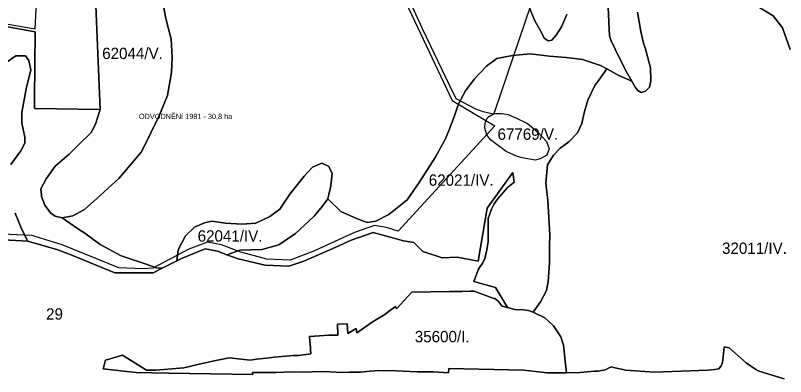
# Model space of a CAD drawing. Extents: x -521621 to -516761, y -1190184 to -1184927.
# Drawn here: x -519686 to -518666, y -1187173 to -1186696 of the extents above; entities that cross this region are included whole.
import ezdxf

# ---------------------------------------------------------------- set-up
doc = ezdxf.new("R2010")
doc.units = 0
doc.layers.add('BPEJ_s', color=7, linetype='Continuous')
doc.layers.add('odvodneni_s', color=7, linetype='Continuous')

msp = doc.modelspace()

# ---------------------------------------------------------------- linework, layer by layer
at = {"layer": 'BPEJ_s'}
for p, q in [((-519061.2, -1186950.7), (-519027.5, -1186903.5)), ((-519027.5, -1186903.5), (-519025.7, -1186916.1)), ((-519025.7, -1186916.1), (-519034.2, -1186923.4)), ((-519034.2, -1186923.4), (-519047.7, -1186938.8)), ((-519052.2, -1186945), (-519055.4, -1186952)), ((-519047.7, -1186938.8), (-519052.2, -1186945)), ((-519073.3, -1187020.7), (-519061.2, -1186950.7)), ((-519055.4, -1186952), (-519060.1, -1186964.4)), ((-519060.1, -1186964.4), (-519060.1, -1186994.7)), ((-519241.2, -1186992.8), (-519212, -1186982.9)), ((-519212, -1186982.9), (-519172, -1186993.8)), ((-519717.5, -1186991.5), (-519669.4, -1186994.1)), ((-519669.4, -1186994.1), (-519629.4, -1187005.5)), ((-519262.3, -1187002.7), (-519241.2, -1186992.8)), ((-519172, -1186993.8), (-519158.4, -1186996.1)), ((-519158.4, -1186996.1), (-519146.6, -1187007.9)), ((-519060.1, -1186994.7), (-519061.7, -1187005.5)), ((-519629.4, -1187005.5), (-519613.1, -1187012)), ((-519465.9, -1187017.1), (-519434.5, -1187004.2)), ((-519434.5, -1187004.2), (-519418.3, -1187007.6)), ((-519418.3, -1187007.6), (-519405.7, -1187012.2)), ((-519303.9, -1187020.8), (-519262.3, -1187002.7)), ((-519146.6, -1187007.9), (-519120.8, -1187016.4)), ((-519061.7, -1187005.5), (-519064.2, -1187017.2)), ((-519613.1, -1187012), (-519553.9, -1187036.2)), ((-519472, -1187020.2), (-519465.9, -1187017.1)), ((-519405.7, -1187012.2), (-519390.7, -1187017.7)), ((-519390.7, -1187017.7), (-519355.3, -1187026)), ((-519120.8, -1187016.4), (-519100.9, -1187015.3)), ((-519100.9, -1187015.3), (-519073.3, -1187020.7)), ((-519064.2, -1187017.2), (-519067.6, -1187023.9)), ((-519503.2, -1187036.2), (-519491.3, -1187030.1)), ((-519491.3, -1187030.1), (-519472, -1187020.2)), ((-519355.3, -1187026), (-519323.8, -1187027.2)), ((-519323.8, -1187027.2), (-519303.9, -1187020.8)), ((-519070.4, -1187027.8), (-519073.4, -1187031.9)), ((-519067.6, -1187023.9), (-519070.4, -1187027.8)), ((-519553.9, -1187036.2), (-519503.2, -1187036.2)), ((-519073.4, -1187031.9), (-519078.8, -1187047.4)), ((-519078.8, -1187047.4), (-519050.4, -1187055.5)), ((-519110.8, -1187060.8), (-519160.9, -1187061.6)), ((-519094.7, -1187060.6), (-519110.8, -1187060.8)), ((-519083.9, -1187060.1), (-519094.7, -1187060.6)), ((-519078.6, -1187060.1), (-519083.9, -1187060.1)), ((-519052.5, -1187069.8), (-519078.6, -1187060.1)), ((-519050.4, -1187055.5), (-519034.3, -1187082.1)), ((-519160.9, -1187061.6), (-519181.5, -1187083.7)), ((-519051.2, -1187070), (-519052.5, -1187069.8)), ((-519046.6, -1187073.7), (-519051.2, -1187070)), ((-519182.6, -1187080.6), (-519190.4, -1187086.5)), ((-519181.5, -1187083.7), (-519182.6, -1187080.6)), ((-519041.4, -1187080.2), (-519046.6, -1187073.7)), ((-519034.3, -1187082.1), (-519041.4, -1187080.2)), ((-519196.7, -1187091.3), (-519212, -1187100.5)), ((-519190.4, -1187086.5), (-519196.7, -1187091.3)), ((-519212, -1187100.5), (-519233.7, -1187115.4)), ((-519246.5, -1187103.5), (-519259.6, -1187104)), ((-519259.6, -1187104), (-519258.9, -1187118.4)), ((-519245.5, -1187116.5), (-519246.5, -1187103.5)), ((-519234.5, -1187109.6), (-519245.5, -1187116.5)), ((-519233.7, -1187115.4), (-519234.5, -1187109.6)), ((-519283.3, -1187119.5), (-519296.6, -1187120.3)), ((-519296.6, -1187120.3), (-519296.1, -1187126.4)), ((-519270.7, -1187118.4), (-519283.3, -1187119.5)), ((-519258.9, -1187118.4), (-519270.7, -1187118.4)), ((-519296.1, -1187126.4), (-519295.3, -1187134.7)), ((-519295.3, -1187134.7), (-519295.1, -1187137.5)), ((-519295.1, -1187137.5), (-519294.6, -1187143.4)), ((-518749.4, -1187151.7), (-518747.8, -1187133.9)), ((-518747.8, -1187133.9), (-518741, -1187135.4)), ((-518741, -1187135.4), (-518718.6, -1187155)), ((-519566.6, -1187151.5), (-519569.4, -1187162.9)), ((-519543.8, -1187144.9), (-519566.6, -1187151.5)), ((-519512.1, -1187164.9), (-519543.8, -1187144.9)), ((-519420.3, -1187151.8), (-519442.3, -1187156.7)), ((-519402.6, -1187148.6), (-519420.3, -1187151.8)), ((-519375, -1187151.4), (-519402.6, -1187148.6)), ((-519366.6, -1187150.2), (-519375, -1187151.4)), ((-519353.4, -1187149), (-519366.6, -1187150.2)), ((-519343.4, -1187147.8), (-519353.4, -1187149)), ((-519332.9, -1187146.6), (-519343.4, -1187147.8)), ((-519318, -1187145.5), (-519332.9, -1187146.6)), ((-519310.7, -1187145.4), (-519318, -1187145.5)), ((-519294.6, -1187143.4), (-519310.7, -1187145.4)), ((-518750.3, -1187156.3), (-518749.4, -1187151.7)), ((-519462.7, -1187161.5), (-519499.6, -1187164.9)), ((-519442.3, -1187156.7), (-519462.7, -1187161.5)), ((-519112.7, -1187168.2), (-519112.1, -1187162.7)), ((-519112.1, -1187162.7), (-519012.8, -1187164.8)), ((-518905.2, -1187164.5), (-518897.3, -1187160.6)), ((-518897.3, -1187160.6), (-518894, -1187161.4)), ((-518894, -1187161.4), (-518877.6, -1187164.9)), ((-518754.9, -1187162.9), (-518751.8, -1187159)), ((-518751.8, -1187159), (-518750.3, -1187156.3)), ((-518718.6, -1187155), (-518705.9, -1187164)), ((-519569.4, -1187162.9), (-519526.2, -1187167.7)), ((-519526.2, -1187167.7), (-519482.7, -1187168.7)), ((-519499.6, -1187164.9), (-519512.1, -1187164.9)), ((-519482.7, -1187168.7), (-519371.4, -1187170.7)), ((-519371.4, -1187170.7), (-519371.8, -1187168.1)), ((-519371.8, -1187168.1), (-519361.1, -1187168.1)), ((-519361.1, -1187168.1), (-519349.9, -1187167.9)), ((-519349.9, -1187167.9), (-519340.9, -1187167.8)), ((-519340.9, -1187167.8), (-519330.4, -1187167.5)), ((-519330.4, -1187167.5), (-519317.6, -1187167.2)), ((-519317.6, -1187167.2), (-519304.5, -1187167.6)), ((-519304.5, -1187167.6), (-519292.7, -1187167)), ((-519292.7, -1187167), (-519282.1, -1187166.5)), ((-519282.1, -1187166.5), (-519269, -1187166.9)), ((-519269, -1187166.9), (-519253.7, -1187167.9)), ((-519253.7, -1187167.9), (-519243.6, -1187167.4)), ((-519243.6, -1187167.4), (-519229, -1187167.4)), ((-519229, -1187167.4), (-519216, -1187166.1)), ((-519216, -1187166.1), (-519204.7, -1187165.1)), ((-519204.7, -1187165.1), (-519197.9, -1187165.6)), ((-519197.9, -1187165.6), (-519191.8, -1187165.2)), ((-519191.8, -1187165.2), (-519153.7, -1187166.8)), ((-519153.7, -1187166.8), (-519132.6, -1187166.8)), ((-519132.6, -1187166.8), (-519112.7, -1187168.2)), ((-519012.8, -1187164.8), (-518989.2, -1187167.6)), ((-518989.2, -1187167.6), (-518982, -1187168.3)), ((-518982, -1187168.3), (-518956.3, -1187168.5)), ((-518956.3, -1187168.5), (-518938.3, -1187168.1)), ((-518938.3, -1187168.1), (-518919.4, -1187166.2)), ((-518919.4, -1187166.2), (-518914.3, -1187166)), ((-518914.3, -1187166), (-518905.2, -1187164.5)), ((-518877.6, -1187164.9), (-518839.9, -1187167.3)), ((-518839.9, -1187167.3), (-518792.7, -1187165.9)), ((-518792.7, -1187165.9), (-518769.1, -1187164.9)), ((-518769.1, -1187164.9), (-518760.6, -1187164)), ((-518760.6, -1187164), (-518754.9, -1187162.9)), ((-518705.9, -1187164), (-518702.8, -1187165.7)), ((-518702.8, -1187165.7), (-518688.4, -1187170)), ((-518688.4, -1187170), (-518668.2, -1187176.1))]:
    msp.add_line(p, q, dxfattribs=at)
for points in [[(-519579.6, -1186671.4), (-519573.7, -1186819.9), (-519660.4, -1186818.6), (-519660.2, -1186805.4), (-519659.7, -1186717.4), (-519752.1, -1186700.7)], [(-519489.7, -1186683.4), (-519486.6, -1186699.5), (-519479.5, -1186727), (-519478.3, -1186750.9), (-519478.9, -1186771.3), (-519484.5, -1186801.4), (-519495.9, -1186829.2), (-519506.3, -1186850.9), (-519518.7, -1186876.2), (-519548.7, -1186911.4), (-519577.7, -1186937.6), (-519594.4, -1186952.4), (-519609.6, -1186960.5), (-519623.9, -1186963.3), (-519632.9, -1186961), (-519639.1, -1186956.7), (-519646.8, -1186946.7), (-519651.1, -1186934.9), (-519651.1, -1186932.7), (-519652, -1186924.8), (-519644.8, -1186911.9), (-519632.9, -1186895.2), (-519614.4, -1186879), (-519603.2, -1186867.6), (-519585.4, -1186850.6), (-519579.6, -1186839.5), (-519573.7, -1186819.9), (-519579.6, -1186671.4)], [(-518901.2, -1186685.2), (-518899.4, -1186722.4), (-518897, -1186729.3), (-518886.5, -1186751.3), (-518876.8, -1186770.2), (-518870, -1186782.6), (-518887, -1186775.1), (-518902.9, -1186766.4), (-518911.3, -1186762), (-518920.6, -1186758.6), (-518935.1, -1186753.9), (-518956.8, -1186751.4), (-518978.8, -1186749.3), (-519004.5, -1186746.5), (-519028, -1186748.4), (-519048.4, -1186752.7), (-519062, -1186762.7), (-519078.1, -1186779.4), (-519090.2, -1186795.2), (-519099.2, -1186812.5), (-519104.7, -1186828.6), (-519111.8, -1186846.9), (-519117.1, -1186859.9), (-519120.8, -1186866.6), (-519130, -1186883.3), (-519151.4, -1186916.7), (-519167.3, -1186939.7), (-519191.5, -1186958.8), (-519208.6, -1186967.9), (-519220.1, -1186969.5), (-519234.4, -1186964.3), (-519255, -1186954.8), (-519272.1, -1186938.1), (-519268.1, -1186921), (-519266.5, -1186904.7), (-519270.9, -1186895.6), (-519280, -1186891.2), (-519292.3, -1186896.4), (-519303.4, -1186908.3), (-519322.5, -1186931.8), (-519335.6, -1186952), (-519349.1, -1186961.5), (-519367.4, -1186970.3), (-519386, -1186971.9), (-519407.8, -1186970.3), (-519425.7, -1186967.9), (-519435.6, -1186969.9), (-519448.7, -1186975.8), (-519460.6, -1186987), (-519470.2, -1187005.6), (-519472, -1187020.2), (-519491.3, -1187030.1), (-519499, -1187029.5), (-519513.9, -1187024.1), (-519545.5, -1187013.4), (-519573.3, -1186998.5), (-519593.9, -1186983.8), (-519603.4, -1186977.6), (-519623.9, -1186963.3), (-519609.6, -1186960.5), (-519594.4, -1186952.4), (-519577.7, -1186937.6), (-519548.7, -1186911.4), (-519518.7, -1186876.2), (-519506.3, -1186850.9), (-519495.9, -1186829.2), (-519484.5, -1186801.4), (-519478.9, -1186771.3), (-519478.3, -1186750.9), (-519479.5, -1186727), (-519486.6, -1186699.5), (-519489.7, -1186683.4)], [(-518955.8, -1186694.2), (-518963.1, -1186710.9), (-518970.1, -1186721.8), (-518975.7, -1186728.5), (-518980.7, -1186729.1), (-518985.7, -1186725.8), (-518988.7, -1186719.8), (-518998.6, -1186701.9), (-519006.3, -1186683.5)], [(-519006.3, -1186683.5), (-518998.6, -1186701.9), (-518988.7, -1186719.8), (-518985.7, -1186725.8), (-518980.7, -1186729.1), (-518975.7, -1186728.5), (-518970.1, -1186721.8), (-518963.1, -1186710.9), (-518955.8, -1186694.2)], [(-518668.2, -1187176.1), (-518688.4, -1187170), (-518702.8, -1187165.7), (-518705.9, -1187164), (-518718.6, -1187155), (-518741, -1187135.4), (-518747.8, -1187133.9), (-518749.4, -1187151.7), (-518750.3, -1187156.3), (-518751.8, -1187159), (-518754.9, -1187162.9), (-518760.6, -1187164), (-518769.1, -1187164.9), (-518792.7, -1187165.9), (-518839.9, -1187167.3), (-518877.6, -1187164.9), (-518894, -1187161.4), (-518897.3, -1187160.6), (-518905.2, -1187164.5), (-518914.3, -1187166), (-518919.4, -1187166.2), (-518938.3, -1187168.1), (-518956.3, -1187168.5), (-518958.2, -1187153), (-518960.5, -1187131.7), (-518963.8, -1187120.9), (-518973.7, -1187106), (-518985.1, -1187095.8), (-519000.4, -1187088.2), (-518990.8, -1187074.3), (-518982.6, -1187059.6), (-518980.8, -1187047.5), (-518978.9, -1187023.1), (-518978.6, -1187000.9), (-518978.5, -1186986), (-518980.9, -1186940.5), (-518983.6, -1186917.6), (-518981.4, -1186893.1), (-518973.5, -1186880.3), (-518964.5, -1186871.3), (-518953.2, -1186862.6), (-518941.6, -1186851.1), (-518936.2, -1186838.6), (-518932.8, -1186824.5), (-518928, -1186807.8), (-518918.9, -1186788.1), (-518913.6, -1186781.3), (-518902.9, -1186766.4), (-518887, -1186775.1), (-518870, -1186782.6), (-518865.5, -1186790.3), (-518861.8, -1186794.8), (-518857.4, -1186797.7), (-518851.6, -1186795.7), (-518846.6, -1186790.4), (-518844.9, -1186781.9), (-518845.1, -1186764.9), (-518852.2, -1186738.4), (-518854.4, -1186732.1), (-518857.9, -1186716.8), (-518862.2, -1186691.2)], [(-518862.2, -1186691.2), (-518857.9, -1186716.8), (-518854.4, -1186732.1), (-518852.2, -1186738.4), (-518845.1, -1186764.9), (-518844.9, -1186781.9), (-518846.6, -1186790.4), (-518851.6, -1186795.7), (-518857.4, -1186797.7), (-518861.8, -1186794.8), (-518865.5, -1186790.3), (-518870, -1186782.6), (-518876.8, -1186770.2), (-518886.5, -1186751.3), (-518897, -1186729.3), (-518899.4, -1186722.4), (-518901.2, -1186685.2)], [(-518660.4, -1186740.5), (-518670.3, -1186712), (-518683, -1186696.2), (-518703, -1186683.7)], [(-518703, -1186683.7), (-518683, -1186696.2), (-518670.3, -1186712), (-518660.4, -1186740.5)], [(-519752.1, -1186700.7), (-519659.7, -1186717.4), (-519660.2, -1186805.4), (-519660.4, -1186818.6), (-519573.7, -1186819.9), (-519579.6, -1186839.5), (-519585.4, -1186850.6), (-519603.2, -1186867.6), (-519614.4, -1186879), (-519632.9, -1186895.2), (-519644.8, -1186911.9), (-519652, -1186924.8), (-519651.1, -1186932.7), (-519651.1, -1186934.9), (-519646.8, -1186946.7), (-519639.1, -1186956.7), (-519632.9, -1186961), (-519623.9, -1186963.3), (-519603.4, -1186977.6), (-519593.9, -1186983.8), (-519573.3, -1186998.5), (-519545.5, -1187013.4), (-519513.9, -1187024.1), (-519499, -1187029.5), (-519491.3, -1187030.1), (-519503.2, -1187036.2), (-519553.9, -1187036.2), (-519613.1, -1187012), (-519629.4, -1187005.5), (-519669.4, -1186994.1), (-519677.2, -1186978.6), (-519685.8, -1186957.2)], [(-519697.7, -1186758), (-519685.3, -1186749), (-519672.5, -1186749), (-519667.7, -1186755.2), (-519665.3, -1186767.6), (-519671.5, -1186792.8), (-519677.2, -1186823.8), (-519677.2, -1186838.1), (-519673.4, -1186856.6), (-519673.4, -1186864.7), (-519678.7, -1186874.7), (-519691.5, -1186892.8)], [(-519691.5, -1186892.8), (-519678.7, -1186874.7), (-519673.4, -1186864.7), (-519673.4, -1186856.6), (-519677.2, -1186838.1), (-519677.2, -1186823.8), (-519671.5, -1186792.8), (-519665.3, -1186767.6), (-519667.7, -1186755.2), (-519672.5, -1186749), (-519685.3, -1186749), (-519697.7, -1186758)], [(-519685.8, -1186957.2), (-519677.2, -1186978.6), (-519669.4, -1186994.1), (-519717.5, -1186991.5)]]:
    msp.add_lwpolyline(points, dxfattribs=at)
for points in [[(-519405.7, -1187012.2), (-519388.8, -1187006), (-519359.4, -1187005.2), (-519337.2, -1186998.9), (-519315, -1186984.2), (-519290.3, -1186961.1), (-519279.6, -1186948.4), (-519272.1, -1186938.1), (-519255, -1186954.8), (-519234.4, -1186964.3), (-519220.1, -1186969.5), (-519208.6, -1186967.9), (-519191.5, -1186958.8), (-519167.3, -1186939.7), (-519151.4, -1186916.7), (-519130, -1186883.3), (-519120.8, -1186866.6), (-519117.1, -1186859.9), (-519111.8, -1186846.9), (-519104.7, -1186828.6), (-519099.2, -1186812.5), (-519090.2, -1186795.2), (-519078.1, -1186779.4), (-519062, -1186762.7), (-519048.4, -1186752.7), (-519028, -1186748.4), (-519004.5, -1186746.5), (-518978.8, -1186749.3), (-518956.8, -1186751.4), (-518935.1, -1186753.9), (-518920.6, -1186758.6), (-518911.3, -1186762), (-518902.9, -1186766.4), (-518913.6, -1186781.3), (-518918.9, -1186788.1), (-518928, -1186807.8), (-518932.8, -1186824.5), (-518936.2, -1186838.6), (-518941.6, -1186851.1), (-518953.2, -1186862.6), (-518964.5, -1186871.3), (-518973.5, -1186880.3), (-518981.4, -1186893.1), (-518983.6, -1186917.6), (-518980.9, -1186940.5), (-518978.5, -1186986), (-518978.6, -1187000.9), (-518978.9, -1187023.1), (-518980.8, -1187047.5), (-518982.6, -1187059.6), (-518990.8, -1187074.3), (-519000.4, -1187088.2), (-519006.5, -1187085.9), (-519013.1, -1187084.8), (-519024.5, -1187084.6), (-519034.3, -1187082.1), (-519050.4, -1187055.5), (-519078.8, -1187047.4), (-519073.4, -1187031.9), (-519070.4, -1187027.8), (-519067.6, -1187023.9), (-519064.2, -1187017.2), (-519061.7, -1187005.5), (-519060.1, -1186994.7), (-519060.1, -1186964.4), (-519055.4, -1186952), (-519052.2, -1186945), (-519047.7, -1186938.8), (-519034.2, -1186923.4), (-519025.7, -1186916.1), (-519027.5, -1186903.5), (-519061.2, -1186950.7), (-519073.3, -1187020.7), (-519100.9, -1187015.3), (-519120.8, -1187016.4), (-519146.6, -1187007.9), (-519158.4, -1186996.1), (-519172, -1186993.8), (-519212, -1186982.9), (-519241.2, -1186992.8), (-519262.3, -1187002.7), (-519303.9, -1187020.8), (-519323.8, -1187027.2), (-519355.3, -1187026), (-519390.7, -1187017.7)], [(-519052, -1186825.3), (-519042.4, -1186825.3), (-519033.4, -1186826.8), (-519022.6, -1186831.6), (-519008, -1186838.6), (-518994.2, -1186849.8), (-518982.6, -1186862.4), (-518979.4, -1186872), (-518982.2, -1186880.3), (-518991.1, -1186885.5), (-518997.7, -1186887.1), (-519014.8, -1186884), (-519022.4, -1186881.6), (-519036.3, -1186875.5), (-519053.2, -1186862.6), (-519057.1, -1186860.1), (-519061.7, -1186853.5), (-519064.5, -1186844.5), (-519064, -1186837.1), (-519060.6, -1186830.2)], [(-519052, -1186825.3), (-519042.4, -1186825.3), (-519033.4, -1186826.8), (-519022.6, -1186831.6), (-519008, -1186838.6), (-518994.2, -1186849.8), (-518982.6, -1186862.4), (-518979.4, -1186872), (-518982.2, -1186880.3), (-518991.1, -1186885.5), (-518997.7, -1186887.1), (-519014.8, -1186884), (-519022.4, -1186881.6), (-519036.3, -1186875.5), (-519053.2, -1186862.6), (-519057.1, -1186860.1), (-519061.7, -1186853.5), (-519064.5, -1186844.5), (-519064, -1186837.1), (-519060.6, -1186830.2)], [(-519472, -1187020.2), (-519470.2, -1187005.6), (-519460.6, -1186987), (-519448.7, -1186975.8), (-519435.6, -1186969.9), (-519425.7, -1186967.9), (-519407.8, -1186970.3), (-519386, -1186971.9), (-519367.4, -1186970.3), (-519349.1, -1186961.5), (-519335.6, -1186952), (-519322.5, -1186931.8), (-519303.4, -1186908.3), (-519292.3, -1186896.4), (-519280, -1186891.2), (-519270.9, -1186895.6), (-519266.5, -1186904.7), (-519268.1, -1186921), (-519272.1, -1186938.1), (-519279.6, -1186948.4), (-519290.3, -1186961.1), (-519315, -1186984.2), (-519337.2, -1186998.9), (-519359.4, -1187005.2), (-519388.8, -1187006), (-519405.7, -1187012.2), (-519418.3, -1187007.6), (-519434.5, -1187004.2), (-519465.9, -1187017.1)], [(-519034.3, -1187082.1), (-519024.5, -1187084.6), (-519013.1, -1187084.8), (-519006.5, -1187085.9), (-519000.4, -1187088.2), (-518985.1, -1187095.8), (-518973.7, -1187106), (-518963.8, -1187120.9), (-518960.5, -1187131.7), (-518958.2, -1187153), (-518956.3, -1187168.5), (-518982, -1187168.3), (-518989.2, -1187167.6), (-519012.8, -1187164.8), (-519112.1, -1187162.7), (-519112.7, -1187168.2), (-519132.6, -1187166.8), (-519153.7, -1187166.8), (-519191.8, -1187165.2), (-519197.9, -1187165.6), (-519204.7, -1187165.1), (-519216, -1187166.1), (-519229, -1187167.4), (-519243.6, -1187167.4), (-519253.7, -1187167.9), (-519269, -1187166.9), (-519282.1, -1187166.5), (-519292.7, -1187167), (-519304.5, -1187167.6), (-519317.6, -1187167.2), (-519330.4, -1187167.5), (-519340.9, -1187167.8), (-519349.9, -1187167.9), (-519361.1, -1187168.1), (-519371.8, -1187168.1), (-519371.4, -1187170.7), (-519482.7, -1187168.7), (-519526.2, -1187167.7), (-519569.4, -1187162.9), (-519566.6, -1187151.5), (-519543.8, -1187144.9), (-519512.1, -1187164.9), (-519499.6, -1187164.9), (-519462.7, -1187161.5), (-519442.3, -1187156.7), (-519420.3, -1187151.8), (-519402.6, -1187148.6), (-519375, -1187151.4), (-519366.6, -1187150.2), (-519353.4, -1187149), (-519343.4, -1187147.8), (-519332.9, -1187146.6), (-519318, -1187145.5), (-519310.7, -1187145.4), (-519294.6, -1187143.4), (-519295.1, -1187137.5), (-519295.3, -1187134.7), (-519296.1, -1187126.4), (-519296.6, -1187120.3), (-519283.3, -1187119.5), (-519270.7, -1187118.4), (-519258.9, -1187118.4), (-519259.6, -1187104), (-519246.5, -1187103.5), (-519245.5, -1187116.5), (-519234.5, -1187109.6), (-519233.7, -1187115.4), (-519212, -1187100.5), (-519196.7, -1187091.3), (-519190.4, -1187086.5), (-519182.6, -1187080.6), (-519181.5, -1187083.7), (-519160.9, -1187061.6), (-519110.8, -1187060.8), (-519094.7, -1187060.6), (-519083.9, -1187060.1), (-519078.6, -1187060.1), (-519052.5, -1187069.8), (-519051.2, -1187070), (-519046.6, -1187073.7), (-519041.4, -1187080.2)]]:
    msp.add_lwpolyline(points, close=True, dxfattribs=at)
at = {"layer": 'odvodneni_s'}
for points in [[(-519752.3, -1186697.3), (-519659.4, -1186713.5), (-519656.7, -1186661.9)], [(-519180.3, -1186654), (-519107.8, -1186808), (-519051.1, -1186841.6), (-519178.9, -1186981), (-519194.7, -1186976.3), (-519210.4, -1186973.4), (-519237, -1186982.9), (-519290, -1187006.8), (-519321.9, -1187019.1), (-519352.7, -1187018), (-519387.2, -1187008.8), (-519413.1, -1186998.9), (-519431.5, -1186995.3), (-519456.3, -1187004.9), (-519503.7, -1187029.7), (-519516.8, -1187030.9), (-519548.9, -1187029.5), (-519623.6, -1186999.2), (-519652.5, -1186990.2), (-519663.4, -1186986.8), (-519714.2, -1186984.7)], [(-519003.5, -1186681.4), (-519051.3, -1186821.6), (-519053.1, -1186826.2), (-519066.5, -1186823.3), (-519076.5, -1186819.5), (-519102.5, -1186806), (-519110.8, -1186788.7), (-519147, -1186713.4), (-519172.9, -1186655.4)]]:
    msp.add_lwpolyline(points, dxfattribs=at)

# ---------------------------------------------------------------- texts
at = {"layer": 'BPEJ_s'}
for s, p in [('62044/V.', (-519570.8, -1186753.3)), ('67769/V.', (-519047.6, -1186860.1)), ('62021/IV.', (-519138.6, -1186920.9)), ('62041/IV.', (-519444.5, -1186994.8)), ('32011/IV.', (-518750.5, -1187011)), ('29', (-519645.1, -1187098)), ('35600/I.', (-519157.1, -1187127.9))]:
    msp.add_text(s, height=15, dxfattribs=at).set_placement(p)
at = {"layer": 'odvodneni_s'}
msp.add_text('ODVODNĚNí 1981 - 30,8 ha', height=7, dxfattribs=at).set_placement((-519522.2, -1186832.7))

doc.saveas('drawing.dxf')
